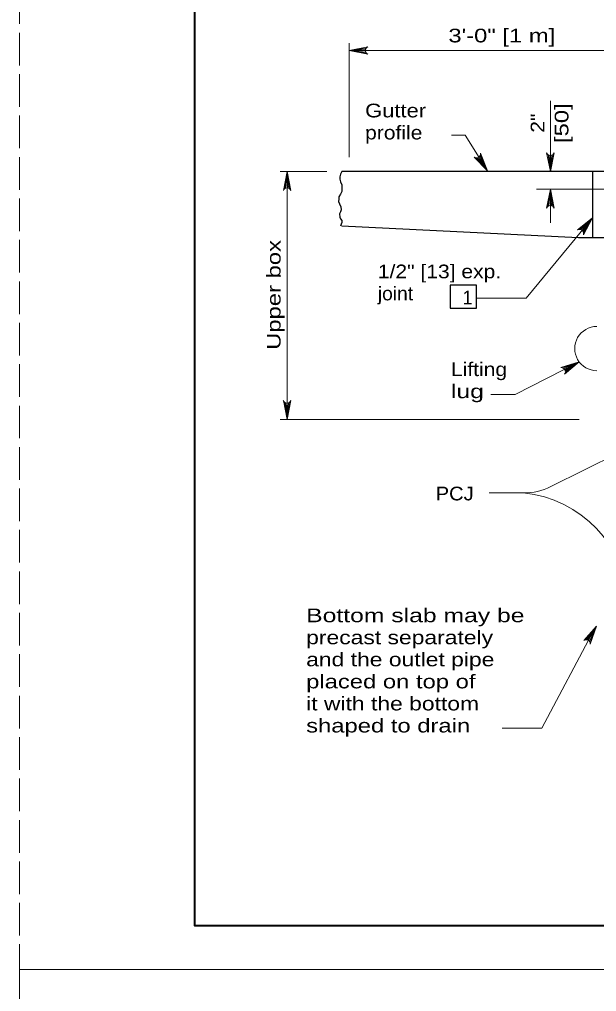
# Model space of a CAD drawing. Extents: x 758.3 to 792.3, y 849.7 to 893.7.
# Drawn here: x 758.32 to 764.9, y 871.44 to 882.51 of the extents above; entities that cross this region are included whole.
import ezdxf
from ezdxf.enums import TextEntityAlignment as Align

# ---------------------------------------------------------------- set-up
doc = ezdxf.new("R2010")
doc.units = 0
doc.header["$LTSCALE"] = 0.062
doc.linetypes.add('LONG_DASHED', pattern=[7.5, 6, -1.5])
doc.layers.add('1', color=7, linetype='Continuous', lineweight=13)

msp = doc.modelspace()

# ---------------------------------------------------------------- linework, layer by layer
at = {"layer": '1'}
for p, q in [((762.0795, 880.9445), (762.0795, 882.24175)), ((762.27333, 882.18533), (762.0795, 882.15817)), ((762.26675, 882.17192), (762.0795, 882.15817)), ((762.0795, 882.15817), (764.10658, 882.15817)), ((762.26483, 882.15817), (762.0795, 882.15817)), ((762.26825, 882.14075), (762.0795, 882.15817)), ((762.27567, 882.12825), (762.0795, 882.15817)), ((764.10658, 882.15817), (765.70775, 882.15817)), ((764.373, 880.77825), (764.373, 881.5865)), ((763.4025, 881.19333), (763.24692, 881.19333)), ((763.65525, 880.78608), (763.4025, 881.19333)), ((763.52808, 880.935), (763.65525, 880.78608)), ((763.54292, 880.93667), (763.65525, 880.78608)), ((763.5555, 880.94233), (763.65525, 880.78608)), ((763.56842, 880.95458), (763.65525, 880.78608)), ((763.575, 880.96767), (763.65525, 880.78608)), ((764.34592, 880.97208), (764.373, 880.77825)), ((764.35933, 880.9655), (764.373, 880.77825)), ((764.403, 880.97442), (764.373, 880.77825)), ((764.3905, 880.967), (764.373, 880.77825)), ((764.373, 880.9635), (764.373, 880.77825)), ((761.82558, 880.77825), (761.29283, 880.77825)), ((761.3415, 880.582), (761.3715, 880.77825)), ((761.35408, 880.58942), (761.3715, 880.77825)), ((761.3715, 880.59292), (761.3715, 880.77825)), ((761.38517, 880.59092), (761.3715, 880.77825)), ((761.39858, 880.58433), (761.3715, 880.77825)), ((761.3715, 880.77825), (761.3715, 877.9565)), ((765.23792, 880.57667), (764.21308, 880.57667)), ((764.34308, 880.3805), (764.373, 880.57667)), ((764.35558, 880.38792), (764.373, 880.57667)), ((764.373, 880.19433), (764.373, 880.57667)), ((764.373, 880.39133), (764.373, 880.57667)), ((764.38675, 880.38933), (764.373, 880.57667)), ((764.40017, 880.38275), (764.373, 880.57667)), ((764.85125, 880.25292), (764.09808, 879.33717)), ((764.70375, 880.12017), (764.85125, 880.25292)), ((764.71808, 880.11792), (764.85125, 880.25292)), ((764.73375, 880.10958), (764.85125, 880.25292)), ((764.74317, 880.09933), (764.85125, 880.25292)), ((764.74933, 880.08567), (764.85125, 880.25292)), ((764.09808, 879.33717), (763.5305, 879.33717)), ((764.51425, 878.54275), (764.70092, 878.61025)), ((764.52683, 878.53525), (764.70092, 878.61025)), ((764.53817, 878.52158), (764.70092, 878.61025)), ((764.54292, 878.50858), (764.70092, 878.61025)), ((764.54358, 878.49367), (764.70092, 878.61025)), ((761.34433, 878.15042), (761.3715, 877.9565)), ((761.35775, 878.14383), (761.3715, 877.9565)), ((761.40142, 878.15267), (761.3715, 877.9565)), ((761.38892, 878.14525), (761.3715, 877.9565)), ((761.3715, 878.14183), (761.3715, 877.9565)), ((764.70258, 877.9565), (761.29283, 877.9565)), ((764.376, 877.19192), (765.47942, 877.73608)), ((764.06683, 877.11933), (763.675, 877.11933)), ((764.77625, 875.4465), (764.897, 875.60058)), ((764.79117, 875.44542), (764.897, 875.60058)), ((764.804, 875.44033), (764.897, 875.60058)), ((764.81733, 875.42858), (764.897, 875.60058)), ((764.8245, 875.41583), (764.897, 875.60058)), ((764.87125, 875.56067), (764.274, 874.44025)), ((764.274, 874.44025), (763.8245, 874.44025))]:
    msp.add_line(p, q, dxfattribs=at)
at = {"layer": '1', "lineweight": 25}
for p, q in [((779.047, 880.77825), (761.99533, 880.77825)), ((764.85125, 880.77825), (764.85125, 880.02242)), ((764.69333, 880.02242), (761.99508, 880.15642)), ((776.4595, 880.02242), (764.69333, 880.02242))]:
    msp.add_line(p, q, dxfattribs=at)
at = {"layer": '1', "linetype": 'LONG_DASHED'}
for points in [[(758.3205, 871.68817), (792.3205, 871.68817), (792.3205, 893.68817), (758.3205, 893.68817)], [(758.3205, 849.68817), (792.3205, 849.68817), (792.3205, 871.68817), (758.3205, 871.68817)]]:
    msp.add_lwpolyline(points, close=True, dxfattribs=at)
at = {"layer": '1', "lineweight": 25}
for points in [[(791.8205, 872.18817), (760.3205, 872.18817), (760.3205, 893.18817)], [(761.99533, 880.77825), (761.982, 880.74892), (761.97183, 880.72033), (761.97283, 880.69392), (761.981, 880.66342), (761.99417, 880.62683), (761.99625, 880.58917), (761.99417, 880.55358), (761.981, 880.522), (761.96267, 880.4895), (761.95967, 880.46508), (761.9575, 880.43758), (761.96975, 880.41217), (761.984, 880.3755), (761.98708, 880.34192), (761.97892, 880.32158), (761.96975, 880.29725), (761.97283, 880.26067), (761.981, 880.24225), (761.99417, 880.22092), (761.99725, 880.19858), (761.98708, 880.18025), (761.98167, 880.15717)]]:
    msp.add_lwpolyline(points, dxfattribs=at)
at = {"layer": '1', "lineweight": 40}
msp.add_lwpolyline([(760.3205, 893.18817), (791.8205, 893.18817), (791.8205, 872.18817), (760.3205, 872.18817)], close=True, dxfattribs=at)
at = {"layer": '1'}
for points in [[(762.29367, 882.11533), (762.0795, 882.15817), (762.29367, 882.201)], [(763.57617, 880.98975), (763.65525, 880.78608), (763.50392, 880.94367)], [(764.41583, 880.99242), (764.373, 880.77825), (764.33017, 880.99242)], [(761.32867, 880.564), (761.3715, 880.77825), (761.41433, 880.564)], [(764.33017, 880.3625), (764.373, 880.57667), (764.41583, 880.3625)], [(764.68242, 880.11433), (764.85125, 880.25292), (764.74858, 880.06008)], [(764.70092, 878.61025), (763.97275, 878.23925), (763.69408, 878.23925)], [(764.49233, 878.54542), (764.70092, 878.61025), (764.53333, 878.47017)], [(761.41433, 878.17067), (761.3715, 877.9565), (761.32867, 878.17067)], [(764.82658, 875.39383), (764.897, 875.60058), (764.75242, 875.43683)]]:
    msp.add_lwpolyline(points, dxfattribs=at)
at = {"layer": '1', "lineweight": 25}
msp.add_lwpolyline([(763.23183, 879.48575), (763.23183, 879.22417), (763.5305, 879.22417), (763.5305, 879.48575)], close=True, dxfattribs=at)
at = {"layer": '1'}
for centre, radius, start, end in [((762.31093, 882.15824), 0.04623, 112.08782, 247.91395), ((763.53068, 880.98123), 0.04623, 234.62596, 10.45209), ((764.37299, 881.00968), 0.04623, 202.08782, 337.91395), ((761.37151, 880.54674), 0.04623, 22.08782, 157.91395), ((764.37309, 880.34519), 0.04623, 22.08782, 157.91395), ((764.70459, 880.07383), 0.04623, 342.76647, 118.59259), ((764.49766, 878.49947), 0.04623, 320.66359, 96.48972), ((761.37142, 878.18797), 0.04623, 202.08782, 337.91395), ((764.09406, 877.69945), 0.58061, 267.31584, 299.04706), ((763.93528, 875.79981), 1.32607, 2.61776, 84.30527), ((764.78078, 875.40042), 0.04623, 351.95829, 127.78442)]:
    msp.add_arc(centre, radius, start, end, dxfattribs=at)
msp.add_ellipse((764.90147, 878.7627), major_axis=(0.25196, 0), ratio=0.999895, start_param=1.57079628, end_param=4.71238898, dxfattribs=at)

# ---------------------------------------------------------------- texts
for s, width, p in [('3\'-0" [1 m]', 1.3, (763.21008, 882.25033)), ('Gutter', 1.2, (762.2605, 881.39617)), ('profile', 1.15, (762.2605, 881.145)), ('1/2" [13] exp.', 1.15, (762.40617, 879.56317)), ('joint', 1.05, (762.40617, 879.312)), ('Lifting', 1.15, (763.23917, 878.44892)), ('lug   ', 1.35, (763.23917, 878.19775)), ('PCJ', 1.1, (763.065, 877.03333)), ('Bottom slab may be', 1.35, (761.58875, 875.64542)), ('precast separately', 1.25, (761.58875, 875.39425)), ('and the outlet pipe', 1.25, (761.58875, 875.14308)), ('placed on top of', 1.3, (761.58875, 874.89192)), ('it with the bottom', 1.25, (761.58875, 874.64075)), ('shaped to drain', 1.3, (761.58875, 874.38958))]:
    msp.add_text(s, height=0.156, dxfattribs=dict(at, width=width)).set_placement(p)
for s, width, p in [('[50]', 1.3, (764.57825, 881.3305)), ('2"', 1.15, (764.30425, 881.33042))]:
    msp.add_text(s, height=0.156, rotation=90, dxfattribs=dict(at, width=width)).set_placement(p, align=Align.CENTER)
at = {"layer": '1', "width": 1.3}
msp.add_text('Upper box', height=0.156, rotation=90, dxfattribs=at).set_placement((761.29725, 878.74775))
at = {"layer": '1'}
msp.add_text('1', height=0.156, dxfattribs=at).set_placement((763.37058, 879.26658))

doc.saveas('drawing.dxf')
